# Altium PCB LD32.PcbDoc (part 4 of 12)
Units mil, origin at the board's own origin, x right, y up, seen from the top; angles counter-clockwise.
Board outline 7007.87 x 4368.85 mil, 12 copper layers (Top Layer, Int1 (GND), Int2 (AVDD), Int3 (DVDD), Int4 (GND), Int5 (ST), Int6 (SB), Int8 (AGND), Int7 (AVCC), Int9 (VCCA), Int10 (GND), Bottom Layer), stack 60.136 mil thick; 1165 components, 667 nets, 3910 pads, 2570 vias.
Unrouted connection lines stored in the file: 14.
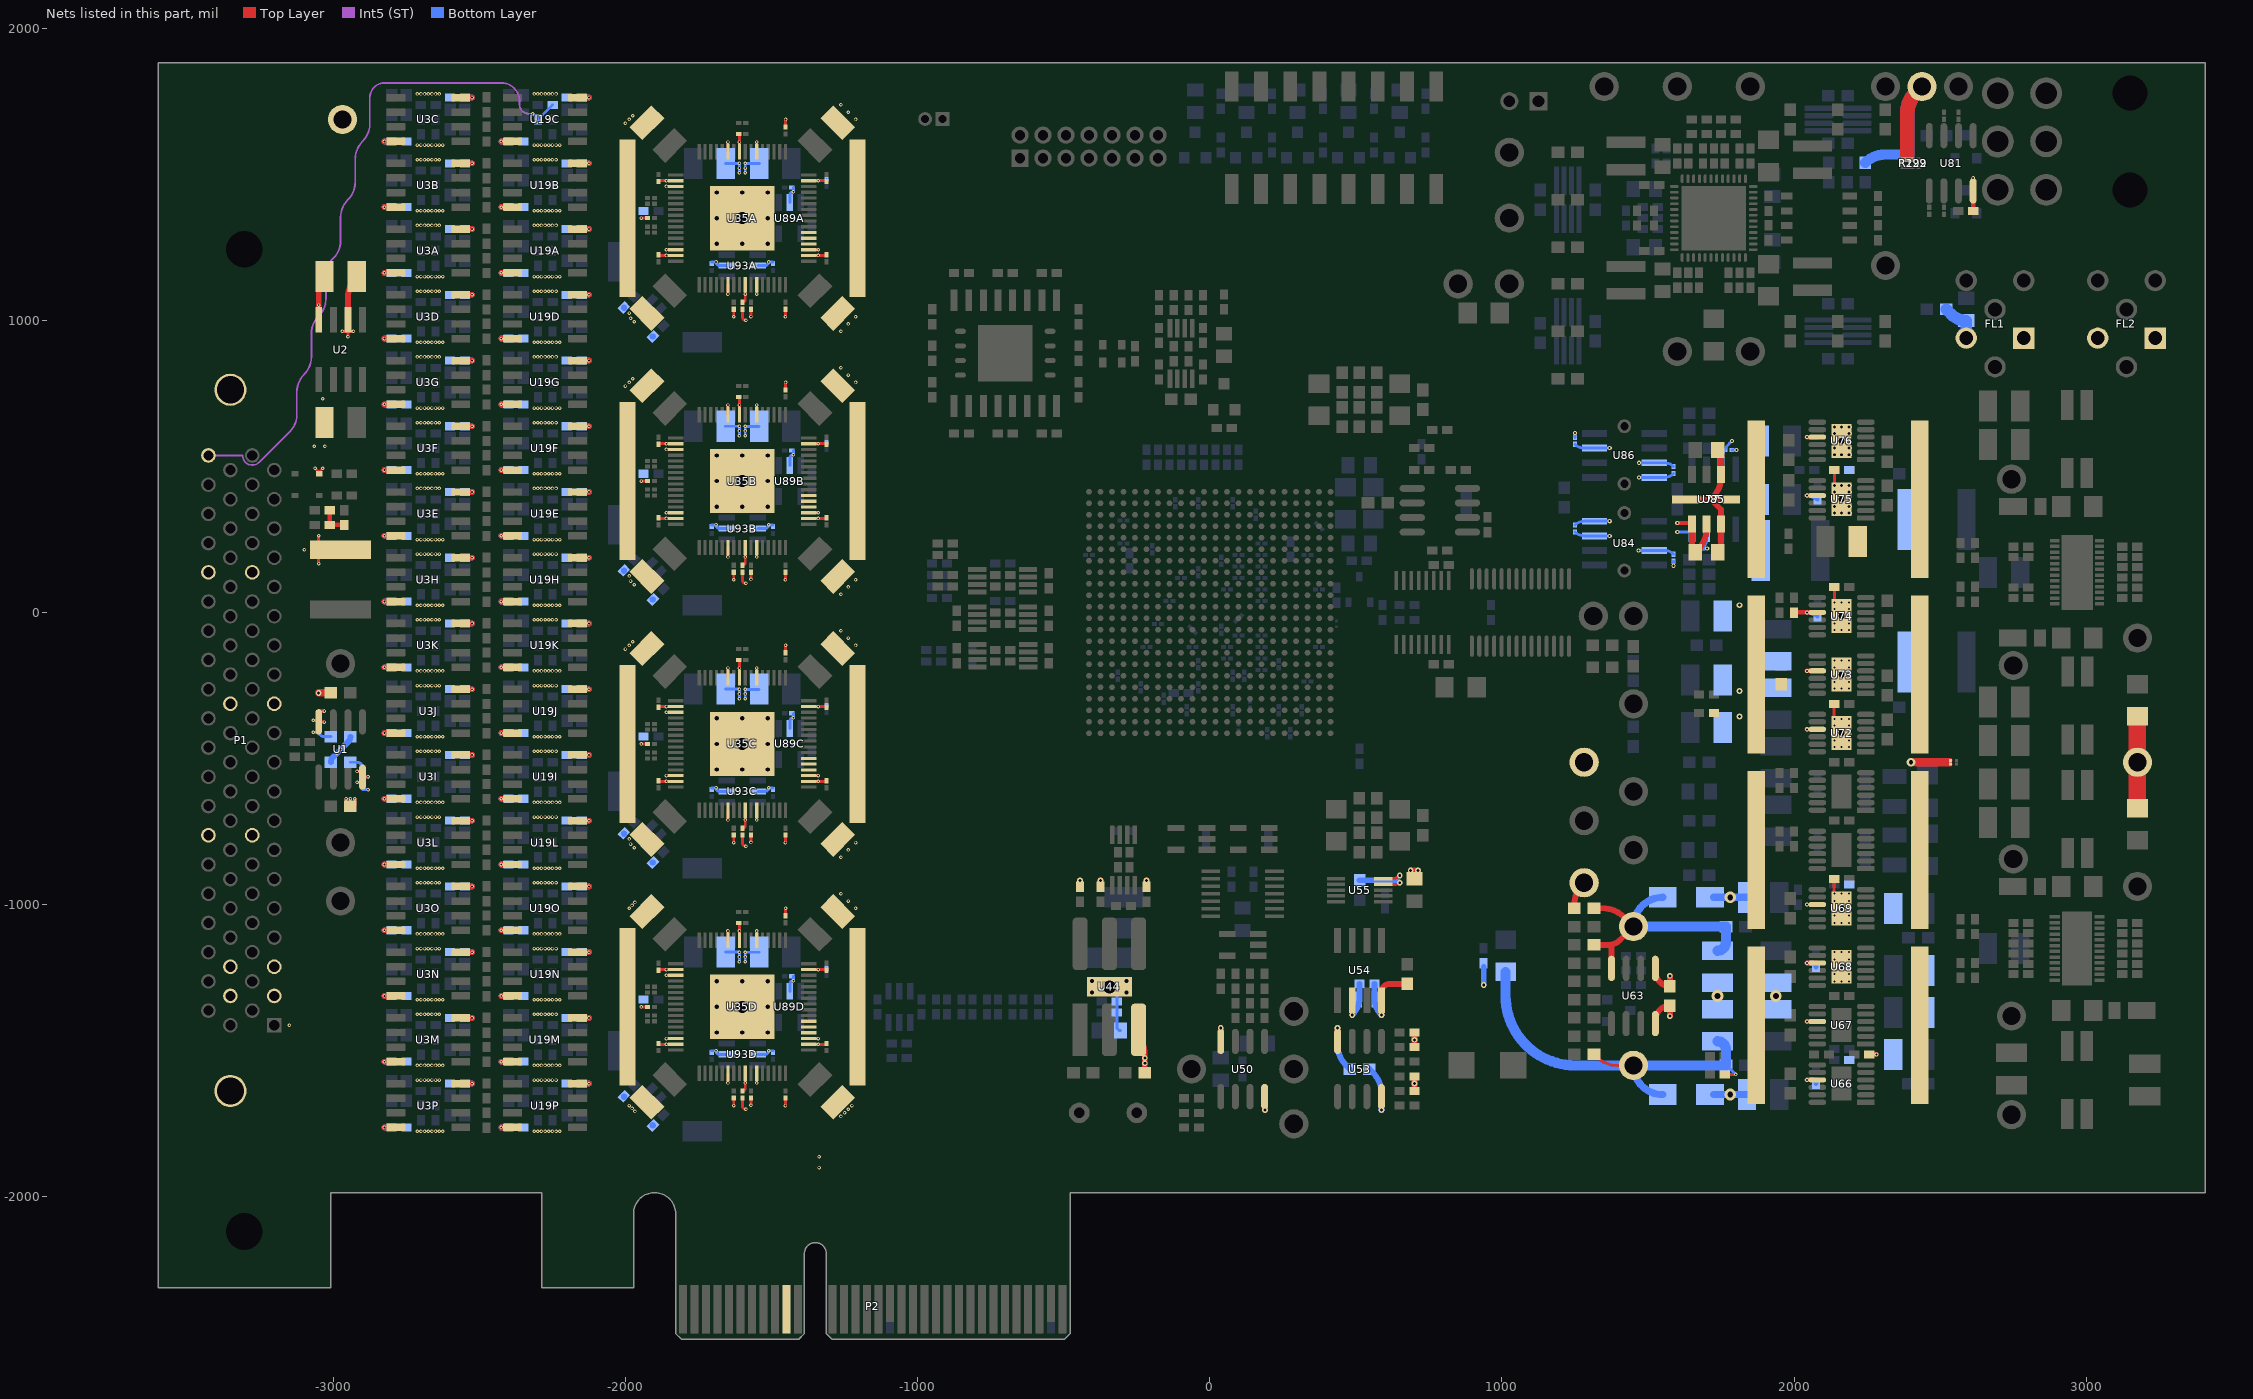
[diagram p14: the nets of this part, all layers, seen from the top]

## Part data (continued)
R213 R215 R216 R218: library part ChipRes1, "R0402 715k", Part Number=ERA-2AEB7150X, Supplier Part Number 1=P715DCCT-ND
R221: library part ChipRes1, "R0603 15k", Part Number=ERA-3AEB153V, Supplier Part Number 1=P15KDBCT-ND
R225 R226: library part ChipRes1, "R0603 0", Part Number=RMCF0603ZT0R00, Supplier Part Number 1=RMCF0603ZT0R00CT-ND
R231: library part ChipRes1, "R0603 34.4k", Part Number=RN73H1JTTD3442F100, Supplier Part Number 1=660-RN73H1JT3442F100
R237: library part ChipRes1, "R0402 12.1k", Part Number=ERA-2AEB1212X, Supplier Part Number 1=P12.1KDCCT-ND
R239: library part ChipRes1, "R0402 33k", Part Number=RT0402FRE0733KL, Supplier Part Number 1=YAG5933CT-ND
R240: library part ChipRes1, "R0402 16.5k", Part Number=RT0402BRD0716K5L, Supplier Part Number 1=YAG4180CT-ND
R243 R245 R262 R270: library part ChipRes1, "R0603 48.1k", Part Number=RT0603BRD0748K1L, Supplier Part Number 1=13-RT0603BRD0748K1LCT-ND
R244: library part ChipRes1, "R0603 59.7k TF", Part Number=RT0603BRD0759K7L, Supplier Part Number 1=13-RT0603BRD0759K7LCT-ND
R251: library part ChipRes1, "R0402 40.2k", Part Number=ERA-2ARC4022X, Supplier Part Number 1=P18270CT-ND
R263: library part ChipRes1, "R0402 9.53k", Part Number=RT0402BRD079K53L, Supplier Part Number 1=YAG4326CT-ND
R264: library part ChipRes1, "R0402 402k", Part Number=RMCF0402FT402KCT-ND
R266: library part ChipRes1, "R0402 301k", Part Number=RMCF0402FT301KCT-ND
R269: library part ChipRes1, "R0402 1.91k", Part Number=RT0402BRD071K91L, Supplier Part Number 1=YAG4201CT-ND
R274 R275: library part ChipRes1, "R0402 30k", Part Number=ERA-2AEB303X, Supplier Part Number 1=P30KDCCT-ND
R284: library part ChipRes1, "R0402 10", Part Number=RP73PF1E10RBTD, Supplier Part Number 1=A127127CT-ND
R308: library part ChipRes1, "R0402  2.67k", Part Number=ERA-2AEB2671X, Supplier Part Number 1=P2.67KDCCT-ND
R317: library part ChipRes1, "R0402 15", Part Number=RP73PF1E15RBTD, Supplier Part Number 1=A127144CT-ND
R335A R335B R335C R335D R335E R335F R335G R335H R335I R335J R335K R335L R335M R335N R335O R335P R383A R383B R383C R383D R383E R383F R383G R383H R383I R383J R383K R383L R383M R383N R383O R383P R399A R399B R399C R399D R399E R399F R399G R399H R399I R399J R399K R399L R399M R399N R399O R399P R447A R447B R447C R447D R447E R447F R447G R447H R447I R447J R447K R447L R447M R447N R447O R447P: library part ChipRes1, "R0603 665", Part Number=RQ73C1J665RBTD, Supplier Part Number 1=A139481CT-ND
S1: "DIP Switch, 8 Position, SPST", Part Number=CKN6128CT-ND
TP1 TP5 TP8 TP9 TP10 TP11 TP15 TP18 TP19 TP20 TP21 TP22 TP24 TP25 TP27 TP28 TP29 TP33 TP34 TP35 TP36 TP37 TP38: library part TP_POSITIVE, "Testpoint, red", Part Number="Keystone / 5000", Supplier Part Number 1=36-5000-ND
TP2 TP3 TP4 TP6 TP7 TP26: library part TP_SIGNAL, "Testpoint, yellow", Part Number="Keystone / 5004", Supplier Part Number 1=36-5004-ND
TP12 TP13 TP14 TP16 TP23 TP30 TP32 TP42: library part TP_GND, "Testpoint, black", Part Number="Keystone / 5001", Supplier Part Number 1=36-5001-ND
TP17 TP31: library part TP_NEGATIVE, "Testpoint, white", Part Number="Keystone / 5002", Supplier Part Number 1=36-5002-ND
TP39 TP40: library part TP_SIGNAL, "Testpoint,SMD, micro miniature", Part Number="Keystone / 5017", Supplier Part Number 1=36-5017CT-ND
TP41A TP41B TP41C TP41D TP45A TP45B TP45C TP45D: library part TP_SMD, "Testpoint,SMD, micro miniature", Part Number=36-5017CT-ND
U1 U50 U53 U57 U63 U81: "Precision Rail-to-Rail Input and Output Operational Amplifier", Part Number=OP284FSZ-REEL7, Supplier Part Number 1=OP284FSZ-REEL7CT-ND
U2 U54: library part ADR292ER, "Low-Noise Micropower Precision Voltage Reference", Part Number=ADR4530ARZ-R7, Supplier Part Number 1=ADR4530ARZ-R7CT-ND
U3A U3B U3C U3D U3E U3F U3G U3H U3I U3J U3K U3L U3M U3N U3O U3P U19A U19B U19C U19D U19E U19F U19G U19H U19I U19J U19K U19L U19M U19N U19O U19P: library part CMP-0808-00013-2, "1.1 nV/rtHz Noise, Low Power, Precision Operational Amplifier, 4.5 to 36 V, -40 to 85 degC, 8-pin SOIC (D8), Green (RoHS & no Sb/Br)", Supplier Part Number 1=296-24959-5-ND
U35A U35B U35C U35D: "Flagship 32-Bit HyperStream II 8-Channel Audio DAC", Part Number=ES9038PRO, Supplier Part Number 1=460-ES9038PRO
U39: library part CMP-12948-000005-1, "IC FLASH 128M SPI 133MHZ 16SOIC", Supplier Part Number 1=MT25QU512ABB8ESF-0SIT-ND
U40: library part CMP-12948-000008-1, "NL"
U41 U42 U43 U46 U47: library part SN65LVDS100, "DIFF TRANSLATOR", Part Number=SN65LVDS100DGKR, Supplier Part Number 1=296-39184-1-ND
U44: library part VCXO_BomarSiTime, "Voltage controlled crystal oscillator, differential output, Bomar 14.3 x 8.7mm, or SiTime 7.0 x 5.0mm", Part Number=B1815-BA0S36LK-67.108864
U45: library part CMP-0364-00012-3, "Artix-7 FPGA, 285 User I/Os, 4 GTP, 484-Ball BGA, Speed Grade 2, Industrial Grade, Pb-Free", Supplier Part Number 1=122-1866-ND
U48 U52 U89A U89B U89C U89D: library part SN65LVDT2DBV, "Single LVDS Receiver with 100 Ohm termination", Part Number=SN65LVDT2DBVR, Supplier Part Number 1=296-6896-1-ND
U49: library part 74F74PC, "Dual D-Type Positive Edge-Triggered Flip-Flop", Supplier Part Number 1=296-1241-1-ND
U51: Part Number=296-9845-1-ND
U55: "16 bit ADC, 250kSPS, pseudo differential, serial", Part Number=AD7685BRMZRL7, Supplier Part Number 1=AD7685BRMZRL7CT-ND
U56: "Quad-Bit Dual Supply Transceiver", Part Number=296-18056-1-ND
U58: library part CMP-0798-00217-1, "1.8 to 5.5 V / 2.5 V, CMOS Low-Voltage 2.5 Ohm, 16-Channel Multiplexer, -40 to 85 degC, 28-pin SOP (RU-28), Tube", Part Number=ADG706BRUZ-REEL7, Supplier Part Number 1=ADG706BRUZ-REEL7CT-ND
U59 U60 U65 U79: library part CMP-0944-00088-2, "Low Power, Precision Instrumentation Amplifier, -40 to 125 degC, 8-pin SOP (DGK8), Green (RoHS & no Sb/Br)", Part Number=INA333QDGKRQ1, Supplier Part Number 1=296-INA333QDGKRQ1CT-ND
U61 U62 U78 U80: "NL"
U64: library part ADP5050ACPZ-R7, "Artix 7 Power Supply", Part Number=ADP5050ACPZ-R7CT-ND, Supplier Part Number 1=505-ADP5052ACPZ-R7CT-ND
U66 U67: library part CMP-09138-000085-1, "IC REG LIN NEG ADJ 500MA 12MSOP", Supplier Part Number 1=505-LT3094IMSE#PBF-ND
U68 U69 U70 U71 U72 U73 U74 U75 U76: library part CMP-09138-000053-1, "IC REG LINEAR 0V 500MA 12MSOP", Part Number=LT3045EMSE-1#PBF, Supplier Part Number 1=505-LT3045EMSE-1#PBF-ND
U77: library part CMP-09137-000088-1, "IC VREF SERIES 0.025% 8CLCC", Supplier Part Number 1=505-LTC6655BHLS8-4.096#PBF-ND
U82 U83: library part LT8582, "Dual 3A Boost/Inverting/SEPIC DC/DC Converter with Fault Protection", Part Number=LT8582EDKD#PBF, Supplier Part Number 1=505-LT8582EDKD#PBF-ND
U84 U85 U86: library part OpAmp, "Op Amp", Part Number=ADA4625-1ARDZ-R7, Supplier Part Number 1=505-ADA4625-1ARDZ-R7CT-ND
U87: library part CMP-0367-00158-2, "1.25 V, 50 ppm / degC, 50 uA Series (Bandgap) Voltage Reference, -40 to 125 degC, 3-pin SOT-23 (DBZ), Green (RoHS & no Sb/Br)", Supplier Part Number 1=REF3012AIDBZTCT-ND
U88 U93A U93B U93C U93D: library part SN74LVC1T45, "Single-Bit Dual Supply Transceiver", Part Number=SN74AVC1T45DBVT, Supplier Part Number 1=296-32277-1-ND
W1 W2: library part NetTie1_small, "Tie two nets together", Part Number=NL
W3: library part NetTie1_small
Y1: library part CMP-06255-000005-1, "MEMS OSC XO 100.0000MHZ CMOS SMD", Supplier Part Number 1=576-4966-5-ND

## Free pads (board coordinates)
  round 113.39 hole 125.2 unplated: MH1(-3304.72,-2118.5) MH2(-3304.72,1243.5)

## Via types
v1: diameter 12, hole 6, Top Layer to Bottom Layer, tented both sides, 1500 vias
v2: diameter 19, hole 10, Top Layer to Bottom Layer, tented both sides, 404 vias
v3: diameter 20, hole 10, Top Layer to Bottom Layer, tented both sides, 337 vias
v4: diameter 14, hole 7, Top Layer to Bottom Layer, tented both sides, 212 vias
v5: diameter 30, hole 15, Top Layer to Bottom Layer, tented both sides, 37 vias
v6: diameter 19.68, hole 7.87, Top Layer to Bottom Layer, 25 vias
v7: diameter 40, hole 20, Top Layer to Bottom Layer, tented both sides, 16 vias
v8: diameter 19.02, hole 10, Top Layer to Bottom Layer, tented both sides, 10 vias
v9: diameter 40, hole 20, Top Layer to Bottom Layer, 9 vias
v10: diameter 60, hole 40, Top Layer to Bottom Layer, 5 vias
v11: diameter 25, hole 13, Top Layer to Bottom Layer, 4 vias
v12: diameter 50, hole 25, Top Layer to Bottom Layer, tented both sides, 4 vias
v13: diameter 35, hole 20, Top Layer to Bottom Layer, 2 vias
v14: diameter 50, hole 25, Top Layer to Bottom Layer, 2 vias
v15: diameter 63, hole 45, Top Layer to Bottom Layer, 1 vias
v16: diameter 14.02, hole 7.01, Top Layer to Bottom Layer, tented both sides, 1 vias
v17: diameter 60, hole 40, Top Layer to Bottom Layer, tented both sides, 1 vias

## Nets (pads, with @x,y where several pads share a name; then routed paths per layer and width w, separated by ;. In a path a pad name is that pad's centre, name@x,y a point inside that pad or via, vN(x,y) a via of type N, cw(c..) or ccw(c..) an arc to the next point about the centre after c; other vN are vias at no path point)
3.3Vaux: P2.B10
12V: C146.1 FL1.1 FL2.1 R199.1 R222.4 R229.1 TP29.1 U81.8 | length 761.7
  Top Layer w10: C146.1@2612.5,1376.43 ccw(c2614.52,1376.43) C146.1@2613.09,1375 ; U81.8@2612.5,1443.01 v1(2612.5,1487.5)
  Top Layer w15: C146.1@2612.5,1376.43 U81.8@2612.5,1443.01
  Top Layer w50: 2387.5,1567.5 2387.5,1708.58 cw(c2487.5,1708.58) 2416.79,1779.29 TP29.1@2437.5,1800
  Bottom Layer w35: R229.1@2243.75,1539.71 cw(c2310.83,1472.63) 2310.83,1567.5 2387.5,1567.5
  Bottom Layer w50: 2387.5,1567.5 2387.5,1708.58 cw(c2487.5,1708.58) 2416.79,1779.29 TP29.1@2437.5,1800
12VA: FL2.2 FR4.1 FR5.1 TP37.1 | length 314.8
  Top Layer w60: FR4.1@3175,-669.88 TP37.1@3175,-512.5 FR5.1@3175,-355.12
12VF: C147.1 FL1.2 R224.2 | length 140.9
  Bottom Layer w40: R224.2@2521.06,1037.5 2538.5,1020.06 ccw(c2589.07,1070.64) C147.1@2589.07,999.11 FL1.2@2589.07,939.07
+7V: C3.1 C9.1 C10.1 C11.1 C97.2 C117.2 C166.2 C188.1 C195.2 C196.2 C335A.1 C335B.1 C335C.1 C335D.1 C335E.1 C335F.1 C335G.1 C335H.1 C335I.1 C335J.1 C335K.1 C335L.1 C335M.1 C335N.1 C335O.1 C335P.1 C415A.1 C415B.1 C415C.1 C415D.1 C415E.1 C415F.1 C415G.1 C415H.1 C415I.1 C415J.1 C415K.1 C415L.1 C415M.1 C415N.1 C415O.1 C415P.1 C480.2 D2.1 D8.2 R134.1 R249.1 TP18.1 U1.8 U2.2 U3A.8 U3B.8 U3C.8 U3D.8 U3E.8 U3F.8 U3G.8 U3H.8 U3I.8 U3J.8 U3K.8 U3L.8 U3M.8 U3N.8 U3O.8 U3P.8 U19A.8 U19B.8 U19C.8 U19D.8 U19E.8 U19F.8 U19G.8 U19H.8 U19I.8 U19J.8 U19K.8 U19L.8 U19M.8 U19N.8 U19O.8 U19P.8 U50.8 U53.8 U54.2 U63.8 U77.1 U77.2 U84.7 U85.7 U86.7 | length 4631.5
  Top Layer w10: v1(-3062.5,493.75) -3051.8,483.05 cw(c-3059.85,475) D2.1@-3048.47,475 cw(c-3032.69,475) -3043.84,486.16 v1(-3036.25,493.75) ; v1(-2968.75,962.5) U2.2@-2950,962.5 ; v1(-2950,943.75) U2.2@-2950,962.5 ; U2.2@-2950,1006.25 U2.2@-2950,1002.36 U2.2@-2950,962.5 ; v1(-2931.25,962.5) U2.2@-2950,962.5 ; v1(-2918.75,-581.25) -2900,-581.25 U1.8@-2900,-563.24 U1.8@-2900,-562.5 ; v1(-2918.75,-543.75) -2900,-543.75 U1.8@-2900,-562.5 ; v1(-2881.25,-562.5) U1.8@-2900,-562.5 ; U77.1@1648.56,287.5 cw(c1648.56,286.06) U77.1@1650,286.06
  Top Layer w15: v4(1600,306.25) 1646.6,306.25 cw(c1646.6,302.85) U77.1@1650,302.85
  Top Layer w20: U2.2@-2950,1006.25 -2950,1078.46 cw(c-2850,1078.46) -2920.71,1149.17 C3.1@-2919.88,1150 ; U3P.8@-2563.78,-1612.5 v1(-2525,-1612.5) ; U3M.8@-2563.78,-1387.5 v1(-2525,-1387.5) ; U3N.8@-2563.78,-1162.5 v1(-2525,-1162.5) ; U3O.8@-2563.78,-937.5 v1(-2525,-937.5) ; U3L.8@-2563.78,-712.5 v1(-2525,-712.5) ; U3I.8@-2563.78,-487.5 v1(-2525,-487.5) ; U3J.8@-2563.78,-262.5 v1(-2525,-262.5) ; U3K.8@-2563.78,-37.5 v1(-2525,-37.5) ; U3H.8@-2563.78,187.5 v1(-2525,187.5) ; U3E.8@-2563.78,412.5 v1(-2525,412.5) ; U3F.8@-2563.78,637.5 v1(-2525,637.5) ; U3G.8@-2563.78,862.5 v1(-2525,862.5) ; U3D.8@-2563.78,1087.5 v1(-2525,1087.5) ; U3A.8@-2563.78,1312.5 v1(-2525,1312.5) ; U3B.8@-2563.78,1537.5 v1(-2525,1537.5) ; U3C.8@-2563.78,1762.5 v1(-2525,1762.5) ; U19P.8@-2163.78,-1612.5 v1(-2125,-1612.5) ; U19M.8@-2163.78,-1387.5 v1(-2125,-1387.5) ; U19N.8@-2163.78,-1162.5 v1(-2125,-1162.5) ; U19O.8@-2163.78,-937.5 v1(-2125,-937.5) ; U19L.8@-2163.78,-712.5 v1(-2125,-712.5) ; U19I.8@-2163.78,-487.5 v1(-2125,-487.5) ; U19J.8@-2163.78,-262.5 v1(-2125,-262.5) ; U19K.8@-2163.78,-37.5 v1(-2125,-37.5) ; U19H.8@-2163.78,187.5 v1(-2125,187.5) ; U19E.8@-2163.78,412.5 v1(-2125,412.5) ; U19F.8@-2163.78,637.5 v1(-2125,637.5) ; U19G.8@-2163.78,862.5 v1(-2125,862.5) ; U19D.8@-2163.78,1087.5 v1(-2125,1087.5) ; U19A.8@-2163.78,1312.5 v1(-2125,1312.5) ; U19B.8@-2163.78,1537.5 v1(-2125,1537.5) ; U19C.8@-2163.78,1762.5 v1(-2125,1762.5) ; U50.8@187.5,-1656.99 v3(188.58,-1702.5) ; U53.8@437.5,-1468.01 v3(437.5,-1422.5) ; v3(487.5,-1377.5) U54.2@487.5,-1327.36 ; R134.1@1314.71,-1137.5 1363.76,-1137.5 ccw(c1363.76,-1080.18) 1375,-1136.39 ; C97.2@1314.71,-1012.5 1346.08,-1012.5 cw(c1346.08,-1112.5) 1416.79,-1041.79 TP18.1@1450,-1075 1404.29,-1120.71 cw(c1363.76,-1080.18) 1375,-1136.39 ; U63.8@1375,-1218.01 1375,-1136.39 ; U77.1@1650,302.85 1650,286.06 1650,234.29 ccw(c1689.65,234.29) C117.2@1661.61,206.25 1670.71,215.35 ccw(c1600,286.06) 1700,286.06 U77.2@1700,302.85
  Bottom Layer w10: C480.2@-2941.54,-512.5 -2918.75,-512.5 cw(c-2918.75,-531.25) -2900,-531.25 -2900,-543.75 ; v1(-2918.75,-581.25) -2900,-581.25 ; v1(-2918.75,-543.75) -2900,-543.75 ; v1(-2881.25,-606.25) -2900,-606.25 -2900,-581.25 ; v1(-2881.25,-562.5) -2900,-562.5 ; C11.1@1250,575.56 ccw(c1281.54,607.1) 1281.54,562.5 v4(1368.75,562.5) ; v4(1467.5,212.5) 1555.96,212.5 cw(c1555.96,167.9) C9.1@1587.5,199.44 ; U85.7@1750,489.86 U85.7@1750,509.14 ; U85.7@1750,524.71 U85.7@1750,509.14 ; C10.1@1763.06,556.25 ccw(c1794.6,524.71) C10.1@1760.15,553.04 ; v4@1786.94,587.5 1779.29,579.85 ccw(c1850,509.14) C10.1@1760.15,553.04 ; -2900,-581.25 -2900,-562.5 ; -2900,-562.5 -2900,-543.75 ; U85.7@1750,509.14 cw(c1850,509.14) C10.1@1760.15,553.04
  Bottom Layer w20: C415P.1@-2549.41,-1612.5 v1(-2525,-1612.5) ; C415M.1@-2549.41,-1387.5 v1(-2525,-1387.5) ; C415N.1@-2549.41,-1162.5 v1(-2525,-1162.5) ; C415O.1@-2549.41,-937.5 v1(-2525,-937.5) ; C415L.1@-2549.41,-712.5 v1(-2525,-712.5) ; C415I.1@-2549.41,-487.5 v1(-2525,-487.5) ; C415J.1@-2549.41,-262.5 v1(-2525,-262.5) ; C415K.1@-2549.41,-37.5 v1(-2525,-37.5) ; C415H.1@-2549.41,187.5 v1(-2525,187.5) ; C415E.1@-2549.41,412.5 v1(-2525,412.5) ; C415F.1@-2549.41,637.5 v1(-2525,637.5) ; C415G.1@-2549.41,862.5 v1(-2525,862.5) ; C415D.1@-2549.41,1087.5 v1(-2525,1087.5) ; C415A.1@-2549.41,1312.5 v1(-2525,1312.5) ; C415B.1@-2549.41,1537.5 v1(-2525,1537.5) ; C415C.1@-2549.41,1762.5 v1(-2525,1762.5) ; C335P.1@-2149.41,-1612.5 v1(-2125,-1612.5) ; C335M.1@-2149.41,-1387.5 v1(-2125,-1387.5) ; C335N.1@-2149.41,-1162.5 v1(-2125,-1162.5) ; C335O.1@-2149.41,-937.5 v1(-2125,-937.5) ; C335L.1@-2149.41,-712.5 v1(-2125,-712.5) ; C335I.1@-2149.41,-487.5 v1(-2125,-487.5) ; C335J.1@-2149.41,-262.5 v1(-2125,-262.5) ; C335K.1@-2149.41,-37.5 v1(-2125,-37.5) ; C335H.1@-2149.41,187.5 v1(-2125,187.5) ; C335E.1@-2149.41,412.5 v1(-2125,412.5) ; C335F.1@-2149.41,637.5 v1(-2125,637.5) ; C335G.1@-2149.41,862.5 v1(-2125,862.5) ; C335D.1@-2149.41,1087.5 v1(-2125,1087.5) ; C335A.1@-2149.41,1312.5 v1(-2125,1312.5) ; C335B.1@-2149.41,1537.5 v1(-2125,1537.5) ; C335C.1@-2149.41,1762.5 v1(-2125,1762.5) ; v3(437.5,-1422.5) 437.5,-1479.44 ccw(c537.5,-1479.44) 466.79,-1550.16 C195.2@479.13,-1562.5 ; v3(487.5,-1377.5) ccw(c426.91,-1316.91) 512.6,-1316.91 C196.2@512.6,-1270.69
  Bottom Layer w25: TP18.1@1450,-1075 cw(c1550,-1075) 1550,-975 D8.2@1550.54,-975
  Bottom Layer w35: TP18.1@1450,-1075 R249.1@1766.54,-1075 1766.54,-1128.35 cw(c1737.5,-1128.35) C166.2@1737.5,-1157.38
  other v4: 1787.5,587.5
-7V: C12.1 C13.1 C14.1 C105.2 C165.1 C367A.1 C367B.1 C367C.1 C367D.1 C367E.1 C367F.1 C367G.1 C367H.1 C367I.1 C367J.1 C367K.1 C367L.1 C367M.1 C367N.1 C367O.1 C367P.1 C447A.1 C447B.1 C447C.1 C447D.1 C447E.1 C447F.1 C447G.1 C447H.1 C447I.1 C447J.1 C447K.1 C447L.1 C447M.1 C447N.1 C447O.1 C447P.1 C479.2 D9.1 FR6.1 R140.2 R143.1 R248.1 TP17.1 U1.4 U3A.4 U3B.4 U3C.4 U3D.4 U3E.4 U3F.4 U3G.4 U3H.4 U3I.4 U3J.4 U3K.4 U3L.4 U3M.4 U3N.4 U3O.4 U3P.4 U19A.4 U19B.4 U19C.4 U19D.4 U19E.4 U19F.4 U19G.4 U19H.4 U19I.4 U19J.4 U19K.4 U19L.4 U19M.4 U19N.4 U19O.4 U19P.4 U63.4 U84.4 U85.4 U86.4 | length 4287.6
  Top Layer w10: v1(-3068.75,-410) -3050,-410 U1.4@-3050,-375 ; v1(-3068.75,-368.75) U1.4@-3050,-368.75 ; v1(-3031.25,-375) U1.4@-3050,-375 ; v1(-3031.25,-337.5) -3050,-337.5 U1.4@-3050,-368.75 ; R140.2@1314.71,-1512.5 1322.93,-1520.71 ccw(c1393.64,-1450) 1393.64,-1550 TP17.1@1450,-1550 ; R143.1@1763.09,-1581.25 v1(1800,-1581.25) ; U1.4@-3050,-375 U1.4@-3050,-374.26 U1.4@-3050,-368.75
  Top Layer w20: v1(-2825,-1762.5) U3P.4@-2786.22,-1762.5 ; v1(-2825,-1537.5) U3M.4@-2786.22,-1537.5 ; v1(-2825,-1312.5) U3N.4@-2786.22,-1312.5 ; v1(-2825,-1087.5) U3O.4@-2786.22,-1087.5 ; v1(-2825,-862.5) U3L.4@-2786.22,-862.5 ; v1(-2825,-637.5) U3I.4@-2786.22,-637.5 ; v1(-2825,-412.5) U3J.4@-2786.22,-412.5 ; v1(-2825,-187.5) U3K.4@-2786.22,-187.5 ; v1(-2825,37.5) U3H.4@-2786.22,37.5 ; v1(-2825,262.5) U3E.4@-2786.22,262.5 ; v1(-2825,487.5) U3F.4@-2786.22,487.5 ; v1(-2825,712.5) U3G.4@-2786.22,712.5 ; v1(-2825,937.5) U3D.4@-2786.22,937.5 ; v1(-2825,1162.5) U3A.4@-2786.22,1162.5 ; v1(-2825,1387.5) U3B.4@-2786.22,1387.5 ; v1(-2825,1612.5) U3C.4@-2786.22,1612.5 ; v1(-2425,-1762.5) U19P.4@-2386.22,-1762.5 ; v1(-2425,-1537.5) U19M.4@-2386.22,-1537.5 ; v1(-2425,-1312.5) U19N.4@-2386.22,-1312.5 ; v1(-2425,-1087.5) U19O.4@-2386.22,-1087.5 ; v1(-2425,-862.5) U19L.4@-2386.22,-862.5 ; v1(-2425,-637.5) U19I.4@-2386.22,-637.5 ; v1(-2425,-412.5) U19J.4@-2386.22,-412.5 ; v1(-2425,-187.5) U19K.4@-2386.22,-187.5 ; v1(-2425,37.5) U19H.4@-2386.22,37.5 ; v1(-2425,262.5) U19E.4@-2386.22,262.5 ; v1(-2425,487.5) U19F.4@-2386.22,487.5 ; v1(-2425,712.5) U19G.4@-2386.22,712.5 ; v1(-2425,937.5) U19D.4@-2386.22,937.5 ; v1(-2425,1162.5) U19A.4@-2386.22,1162.5 ; v1(-2425,1387.5) U19B.4@-2386.22,1387.5 ; v1(-2425,1612.5) U19C.4@-2386.22,1612.5 ; U63.4@1525,-1395.82 cw(c1575,-1395.82) C105.2@1575,-1345.82 v8(1575,-1381.25)
  Bottom Layer w10: v1(-3068.75,-410) -3050,-410 -3050,-406.25 ; v1(-3068.75,-368.75) -3050,-368.75 ; v1(-3031.25,-337.5) -3050,-337.5 -3050,-368.75 ; C479.2@-3008.46,-425 -3031.25,-425 cw(c-3031.25,-406.25) -3050,-406.25 ; C14.1@1250,299.44 cw(c1281.54,267.9) 1281.54,312.5 v4(1368.75,312.5) ; v4(1468.75,462.5) 1555.96,462.5 ccw(c1555.96,507.1) C13.1@1587.5,475.56 ; v4(1600,275) U85.4@1650,275 ; U85.4@1650,275.59 U85.4@1650,275 ; U85.4@1650,285.14 U85.4@1650,275 ; C12.1@1663.06,218.75 cw(c1694.6,250.29) 1650,250.29 U85.4@1650,275 ; R248.1@1766.54,-1550 cw(c1766.54,-1555.35) 1770.31,-1551.56 v1(1800,-1581.25) ; -3050,-406.25 -3050,-368.75
  Bottom Layer w20: v1(-2825,-1762.5) C447P.1@-2800.59,-1762.5 ; v1(-2825,-1537.5) C447M.1@-2800.59,-1537.5 ; v1(-2825,-1312.5) C447N.1@-2800.59,-1312.5 ; v1(-2825,-1087.5) C447O.1@-2800.59,-1087.5 ; v1(-2825,-862.5) C447L.1@-2800.59,-862.5 ; v1(-2825,-637.5) C447I.1@-2800.59,-637.5 ; v1(-2825,-412.5) C447J.1@-2800.59,-412.5 ; v1(-2825,-187.5) C447K.1@-2800.59,-187.5 ; v1(-2825,37.5) C447H.1@-2800.59,37.5 ; v1(-2825,262.5) C447E.1@-2800.59,262.5 ; v1(-2825,487.5) C447F.1@-2800.59,487.5 ; v1(-2825,712.5) C447G.1@-2800.59,712.5 ; v1(-2825,937.5) C447D.1@-2800.59,937.5 ; v1(-2825,1162.5) C447A.1@-2800.59,1162.5 ; v1(-2825,1387.5) C447B.1@-2800.59,1387.5 ; v1(-2825,1612.5) C447C.1@-2800.59,1612.5 ; v1(-2425,-1762.5) C367P.1@-2400.59,-1762.5 ; v1(-2425,-1537.5) C367M.1@-2400.59,-1537.5 ; v1(-2425,-1312.5) C367N.1@-2400.59,-1312.5 ; v1(-2425,-1087.5) C367O.1@-2400.59,-1087.5 ; v1(-2425,-862.5) C367L.1@-2400.59,-862.5 ; v1(-2425,-637.5) C367I.1@-2400.59,-637.5 ; v1(-2425,-412.5) C367J.1@-2400.59,-412.5 ; v1(-2425,-187.5) C367K.1@-2400.59,-187.5 ; v1(-2425,37.5) C367H.1@-2400.59,37.5 ; v1(-2425,262.5) C367E.1@-2400.59,262.5 ; v1(-2425,487.5) C367F.1@-2400.59,487.5 ; v1(-2425,712.5) C367G.1@-2400.59,712.5 ; v1(-2425,937.5) C367D.1@-2400.59,937.5 ; v1(-2425,1162.5) C367A.1@-2400.59,1162.5 ; v1(-2425,1387.5) C367B.1@-2400.59,1387.5 ; v1(-2425,1612.5) C367C.1@-2400.59,1612.5
  Bottom Layer w25: TP17.1@1450,-1550 ccw(c1550,-1550) 1550,-1650 D9.1@1550.54,-1650
  Bottom Layer w35: FR6.1@1012.5,-1230.12 1012.5,-1312.36 ccw(c1250.14,-1312.36) 1250.14,-1550 TP17.1@1450,-1550 R248.1@1766.54,-1550 1766.54,-1496.65 ccw(c1737.5,-1496.65) C165.1@1737.5,-1467.62
ADRA: R63A.2 U35A.41 | length 66.2
  Top Layer w10: R63A.2@-1600,1061.94 ccw(c-1600,1071.78) -1590.16,1071.78 -1590.16,1086.93 v1(-1590.16,1090) U35A.41@-1590.16,1122.5
ADRB: R63B.2 U35B.41 | length 66.2
  Top Layer w10: R63B.2@-1600,161.94 ccw(c-1600,171.78) -1590.16,171.78 -1590.16,186.93 v1(-1590.16,190) U35B.41@-1590.16,222.5
ADRC: R63C.2 U35C.41 | length 66.2
  Top Layer w10: R63C.2@-1600,-738.06 ccw(c-1600,-728.22) -1590.16,-728.22 -1590.16,-713.07 v1(-1590.16,-710) U35C.41@-1590.16,-677.5
ADRD: R63D.2 U35D.41 | length 66.2
  Top Layer w10: R63D.2@-1600,-1638.06 ccw(c-1600,-1628.22) -1590.16,-1628.22 -1590.16,-1613.07 v1(-1590.16,-1610) U35D.41@-1590.16,-1577.5
AGND: C1.1 C2.2 C3.2 C4.2 C5.1 C6.2 C7A.1 C7B.1 C7C.1 C7D.1 C8A.2 C8B.2 C8C.2 C8D.2 C9.2 C10.2 C11.2 C12.2 C13.2 C14.2 C15A.1 C15B.1 C15C.1 C15D.1 C19A.1 C19B.1 C19C.1 C19D.1 C20A.1 C20B.1 C20C.1 C20D.1 C27A.1 C27B.1 C27C.1 C27D.1 C31A.1 C31B.1 C31C.1 C31D.1 C35A.2 C35B.2 C35C.2 C35D.2 C36A.2 C36B.2 C36C.2 C36D.2 C43A.2 C43B.2 C43C.2 C43D.2 C44A.1 C44B.1 C44C.1 C44D.1 C51A.1 C51B.1 C51C.1 C51D.1 C52A.1 C52B.1 C52C.1 C52D.1 C64.1 C86.1 C87.1 C88.1 C89.1 C90.2 C97.1 C105.1 C116.2 C117.1 C144.1 C145.2 C150.1 C151.2 C156.1 C157.2 C158.1 C161.1 C162.1 C165.2 C166.1 C167.1 C168.1 C169.1 C170.1 C171.1 C181.1 C188.2 C195.1 C196.1 C198.1 C267.1 C272.2 C287A.2 C287B.2 C287C.2 C287D.2 C291A.1 C291B.1 C291C.1 C291D.1 C295A.2 C295B.2 C295C.2 C295D.2 C299A.1 C299B.1 C299C.1 C299D.1 C303A.1 C303B.1 C303C.1 C303D.1 C307A.1 C307B.1 C307C.1 C307D.1 C311A.2 C311B.2 C311C.2 C311D.2 C315A.2 C315B.2 C315C.2 C315D.2 C335A.2 C335B.2 C335C.2 C335D.2 C335E.2 C335F.2 C335G.2 C335H.2 C335I.2 C335J.2 C335K.2 C335L.2 C335M.2 C335N.2 C335O.2 C335P.2 C367A.2 C367B.2 C367C.2 C367D.2 C367E.2 C367F.2 C367G.2 C367H.2 C367I.2 C367J.2 C367K.2 C367L.2 C367M.2 C367N.2 C367O.2 C367P.2 C415A.2 C415B.2 C415C.2 C415D.2 C415E.2 C415F.2 C415G.2 C415H.2 C415I.2 C415J.2 C415K.2 C415L.2 C415M.2 C415N.2 C415O.2 C415P.2 C447A.2 C447B.2 C447C.2 C447D.2 C447E.2 C447F.2 C447G.2 C447H.2 C447I.2 C447J.2 C447K.2 C447L.2 C447M.2 C447N.2 C447O.2 C447P.2 C479.1 C480.1 C481.2 C482.1 C483.1 C484.2 C500.1 D8.1 D9.2 MP4A.1 MP4A.2 MP4B.1 MP4B.2 MP4C.1 MP4C.2 MP4D.1 MP4D.2 MP5.1 MP5.2 MP6.1 MP6.2 MP7.1 MP7.2 MP8.1 MP8.2 P1.5 P1.6 P1.9 P1.10 P1.27 P1.28 P1.45 P1.46 P1.63 P1.64 P1.81 P1.82 R3.1 R6.1 R55A.1 R55B.1 R55C.1 R55D.1 R63A.1 R63B.1 R63C.1 R63D.1 R91.1 R94.2 R97.2 R117.2 R149.2 R151.2 R160.2 R172.2 R177.2 R178.2 R179.2 R181.1 R186.1 R232.2 R234.2 R239.1 R240.1 R241.2 R242.1 R303.2 R327A.1 R327B.1 R327C.1 R327D.1 TP12.1 TP14.1 TP42.1 U2.4 U35A.6 U35A.9 U35A.11 U35A.18 U35A.19 U35A.30 U35A.31 U35A.38 U35A.43 U35A.50 U35A.51 U35A.52 U35A.53 U35A.54 U35A.63 U35A.65 U35B.6 U35B.9 U35B.11 U35B.18 U35B.19 U35B.30 U35B.31 U35B.38 U35B.43 U35B.50 U35B.51 U35B.52 U35B.53 U35B.54 U35B.63 U35B.65 U35C.6 U35C.9 U35C.11 U35C.18 U35C.19 U35C.30 U35C.31 U35C.38 U35C.43 U35C.50 U35C.51 U35C.52 U35C.53 U35C.54 U35C.63 U35C.65 U35D.6 U35D.9 U35D.11 U35D.18 U35D.19 U35D.30 U35D.31 U35D.38 U35D.43 U35D.50 U35D.51 U35D.52 U35D.53 U35D.54 U35D.63 U35D.65 U44.3 U44.7 U50.4 U53.4 U54.4 U55.4 U55.5 U63.5 U66.9 U67.9 U68.9 U68.13 U69.9 U69.13 U72.9 U72.13 U73.9 U73.13 U74.9 U74.13 U75.9 U75.13 U76.9 U76.13 U77.3 U77.4 U77.5 U77.8 U84.3 U85.3 U86.3 U89A.2 U89B.2 U89C.2 U89D.2 U93A.2 U93A.5 U93B.2 U93B.5 U93C.2 U93C.5 U93D.2 U93D.5 W1.2 W2.2 | length 8504.6
  Top Layer w10: v1(-3050,167.5) v1(-3050,262.5) ; v1(-2956.25,-637.5) -2956.25,-662.5 C4.2@-2941.54,-662.5 ; v1(-2941.25,-637.5) -2941.54,-637.5 C4.2@-2941.54,-662.5 ; v1(-2926.25,-637.5) -2926.25,-662.5 C4.2@-2941.54,-662.5 ; v1(-1946.08,-1350) C15D.1@-1930,-1350 ; v1(-1946.08,-450) C15C.1@-1930,-450 ; v1(-1946.08,450) C15B.1@-1930,450 ; v1(-1946.08,1350) C15A.1@-1930,1350 ; C19D.1@-1887.5,-1475.56 ccw(c-1885.11,-1475.56) -1885.11,-1477.95 -1868.3,-1477.95 v1(-1860,-1477.95) U35D.31@-1827.5,-1477.95 ; C20D.1@-1887.5,-1224.44 cw(c-1885.11,-1224.44) -1885.11,-1222.05 -1868.3,-1222.05 v1(-1860,-1222.05) U35D.18@-1827.5,-1222.05 ; C19C.1@-1887.5,-575.56 ccw(c-1885.11,-575.56) -1885.11,-577.95 -1868.3,-577.95 v1(-1860,-577.95) U35C.31@-1827.5,-577.95 ; C20C.1@-1887.5,-324.44 cw(c-1885.11,-324.44) -1885.11,-322.05 -1868.3,-322.05 v1(-1860,-322.05) U35C.18@-1827.5,-322.05 ; C19B.1@-1887.5,324.44 ccw(c-1885.11,324.44) -1885.11,322.05 -1868.3,322.05 v1(-1860,322.05) U35B.31@-1827.5,322.05 ; C20B.1@-1887.5,575.56 cw(c-1885.11,575.56) -1885.11,577.95 -1868.3,577.95 v1(-1860,577.95) U35B.18@-1827.5,577.95 ; C19A.1@-1887.5,1224.44 ccw(c-1885.11,1224.44) -1885.11,1222.05 -1868.3,1222.05 v1(-1860,1222.05) U35A.31@-1827.5,1222.05 ; C20A.1@-1887.5,1475.56 cw(c-1885.11,1475.56) -1885.11,1477.95 -1868.3,1477.95 v1(-1860,1477.95) U35A.18@-1827.5,1477.95 ; v1(-1860,-1458.27) U35D.30@-1827.5,-1458.27 ; v1(-1860,-1241.73) U35D.19@-1827.5,-1241.73 ; v1(-1860,-558.27) U35C.30@-1827.5,-558.27 ; v1(-1860,-341.73) U35C.19@-1827.5,-341.73 ; v1(-1860,341.73) U35B.30@-1827.5,341.73 ; v1(-1860,558.27) U35B.19@-1827.5,558.27 ; v1(-1860,1241.73) U35A.30@-1827.5,1241.73 ; v1(-1860,1458.27) U35A.19@-1827.5,1458.27 ; v1(-1649.21,-1610) U35D.38@-1649.21,-1577.5 ; U35D.11@-1649.21,-1122.5 v1(-1649.21,-1090) ; v1(-1649.21,-710) U35C.38@-1649.21,-677.5 ; U35C.11@-1649.21,-222.5 v1(-1649.21,-190) ; v1(-1649.21,190) U35B.38@-1649.21,222.5 ; U35B.11@-1649.21,677.5 v1(-1649.21,710) ; v1(-1649.21,1090) U35A.38@-1649.21,1122.5 ; U35A.11@-1649.21,1577.5 v1(-1649.21,1610) ; v1(-1629.53,-1687.5) C27D.1@-1629.53,-1667.5 ; v1(-1629.53,-787.5) C27C.1@-1629.53,-767.5 ; v1(-1629.53,112.5) C27B.1@-1629.53,132.5 ; v1(-1629.53,1012.5) C27A.1@-1629.53,1032.5 ; R55D.1@-1611.94,-1062.5 cw(c-1611.94,-1064.59) -1609.84,-1064.59 -1609.84,-1088.64 v1(-1609.84,-1090) U35D.9@-1609.84,-1122.5 ; R55C.1@-1611.94,-162.5 cw(c-1611.94,-164.59) -1609.84,-164.59 -1609.84,-188.64 v1(-1609.84,-190) U35C.9@-1609.84,-222.5 ; R55B.1@-1611.94,737.5 cw(c-1611.94,735.41) -1609.84,735.41 -1609.84,711.36 v1(-1609.84,710) U35B.9@-1609.84,677.5 ; R55A.1@-1611.94,1637.5 cw(c-1611.94,1635.41) -1609.84,1635.41 -1609.84,1611.36 v1(-1609.84,1610) U35A.9@-1609.84,1577.5 ; R63D.1@-1600,-1661.94 -1600,-1687.5 ccw(c-1587.5,-1687.5) v1(-1587.5,-1700) ; R63C.1@-1600,-761.94 -1600,-787.5 ccw(c-1587.5,-787.5) v1(-1587.5,-800) ; R63B.1@-1600,138.06 -1600,112.5 ccw(c-1587.5,112.5) v1(-1587.5,100) ; R63A.1@-1600,1038.06 -1600,1012.5 ccw(c-1587.5,1012.5) v1(-1587.5,1000) ; v1(-1570.47,-1686.91) C31D.1@-1570.47,-1667.5 ; v1(-1570.47,-786.91) C31C.1@-1570.47,-767.5 ; v1(-1570.47,113.09) C31B.1@-1570.47,132.5 ; v1(-1570.47,1013.09) C31A.1@-1570.47,1032.5 ; v1(-1550.79,-1610) U35D.43@-1550.79,-1577.5 ; U35D.6@-1550.79,-1122.5 v1(-1550.79,-1090) ; v1(-1550.79,-710) U35C.43@-1550.79,-677.5 ; U35C.6@-1550.79,-222.5 v1(-1550.79,-190) ; v1(-1550.79,190) U35B.43@-1550.79,222.5 ; U35B.6@-1550.79,677.5 v1(-1550.79,710) ; v1(-1550.79,1090) U35A.43@-1550.79,1122.5 ; U35A.6@-1550.79,1577.5 v1(-1550.79,1610) ; v1(-1452.5,-1687.5) -1452.21,-1687.21 C35D.2@-1452.21,-1667.5 ; v1(-1452.5,-787.5) -1452.21,-787.21 C35C.2@-1452.21,-767.5 ; v1(-1452.5,112.5) -1452.21,112.79 C35B.2@-1452.21,132.5 ; v1(-1452.5,1012.5) -1452.21,1012.79 C35A.2@-1452.21,1032.5 ; C36D.2@-1452.21,-1032.5 v1(-1452.21,-1012.38) ; C36C.2@-1452.21,-132.5 v1(-1452.21,-112.38) ; C36B.2@-1452.21,767.5 v1(-1452.21,787.62) ; C36A.2@-1452.21,1667.5 v1(-1452.21,1687.62) ; U35D.50@-1372.5,-1477.95 v1(-1340,-1477.95) -1331.7,-1477.95 -1314.89,-1477.95 ccw(c-1314.89,-1475.56) C51D.1@-1312.5,-1475.56 ; U35D.51@-1372.5,-1458.27 v1(-1340,-1458.27) ; U35D.63@-1372.5,-1222.05 v1(-1340,-1222.05) -1331.7,-1222.05 -1314.89,-1222.05 cw(c-1314.89,-1224.44) C52D.1@-1312.5,-1224.44 ; U35C.50@-1372.5,-577.95 v1(-1340,-577.95) -1331.7,-577.95 -1314.89,-577.95 ccw(c-1314.89,-575.56) C51C.1@-1312.5,-575.56 ; U35C.51@-1372.5,-558.27 v1(-1340,-558.27) ; U35C.63@-1372.5,-322.05 v1(-1340,-322.05) -1331.7,-322.05 -1314.89,-322.05 cw(c-1314.89,-324.44) C52C.1@-1312.5,-324.44 ; U35B.50@-1372.5,322.05 v1(-1340,322.05) -1331.7,322.05 -1314.89,322.05 ccw(c-1314.89,324.44) C51B.1@-1312.5,324.44 ; U35B.51@-1372.5,341.73 v1(-1340,341.73) ; U35B.63@-1372.5,577.95 v1(-1340,577.95) -1331.7,577.95 -1314.89,577.95 cw(c-1314.89,575.56) C52B.1@-1312.5,575.56 ; U35A.50@-1372.5,1222.05 v1(-1340,1222.05) -1331.7,1222.05 -1314.89,1222.05 ccw(c-1314.89,1224.44) C51A.1@-1312.5,1224.44 ; U35A.51@-1372.5,1241.73 v1(-1340,1241.73) ; U35A.63@-1372.5,1477.95 v1(-1340,1477.95) -1331.7,1477.95 -1314.89,1477.95 cw(c-1314.89,1475.56) C52A.1@-1312.5,1475.56 ; U55.4@593.21,-930.31 637.17,-930.31 ccw(c637.17,-912.17) v3(650,-925) ; U55.5@593.21,-910.63 624.34,-910.63 ccw(c624.34,-874.34) v3(650,-900) ; R181.1@2136.91,-912.5 2136.91,-962.5 v4(2137.5,-962.5) ; R177.2@2136.91,-312.5 2136.91,-365 v4(2137.5,-365) ; R178.2@2136.91,87.5 2137.5,87.5 v4(2137.5,35) ; R179.2@2136.91,487.5 2137.5,487.5 v3(2137.5,435)
  Top Layer w15: C2.2@-3011.91,350 R3.1@-3011.91,300 R6.1@-2963.09,300 ; R172.2@2000,-0.59 cw(c2002.14,-2.73) 2002.14,0.3 v4(2043.75,0.3) U74.9@2079.44,0.3 ; v4(2043.75,-399.7) U72.9@2079.44,-399.7 ; v4(2043.75,-199.7) U73.9@2079.44,-199.7 ; v4(2043.75,400.3) U75.9@2079.44,400.3 ; v4(2043.75,600.3) U76.9@2079.44,600.3 ; W1.2@2535,-518.75 2415.09,-518.75 cw(c2415.09,-497.41) v5(2400,-512.5) cw(c2415.09,-527.59) 2415.09,-506.25 W2.2@2535,-506.25
  Top Layer w16: v4(2043.75,-1599.7) U66.9@2079.44,-1599.7 ; v4(2043.75,-1400) U67.9@2079.14,-1400 ; v4(2043.75,-1199.7) U68.9@2079.44,-1199.7 ; R186.1@2256.84,-1512.5 v4(2281.25,-1512.5)
  Top Layer w20: U2.4@-3050,1002.36 v1(-3050,1052.5) -3050,1102 cw(c-2982.12,1102) C3.2@-3030.12,1150 ; C64.1@-444.88,-938.98 ccw(c-445.83,-938.03) -444.49,-938.03 v3(-444.49,-917.32) ; R91.1@-374.02,-938.98 v3(-374.02,-917.32) ; U44.3@-246.46,-1452.76 cw(c-304.44,-1510.74) -222.44,-1510.74 R94.2@-222.44,-1574.8 ; R97.2@-216.54,-938.98 v3(-216.54,-917.32) ; U50.4@37.5,-1468.01 v3(37.5,-1422.5) ; v3(587.5,-1377.5) U54.4@587.5,-1327.36 587.5,-1300 cw(c616.54,-1300) 616.54,-1270.96 C89.1@675,-1270.96 ; C86.1@700.59,-1637.5 C87.1@700.59,-1587.5 ; R117.2@700.59,-1487.5 C88.1@700.59,-1437.5 ; C97.1@1247.79,-1012.5 1247.79,-999.89 cw(c1347.79,-999.89) 1277.07,-929.18 TP12.1@1281.25,-925 ; U63.5@1525,-1228.89 ccw(c1575,-1228.89) C105.1@1575,-1278.89 v8(1575,-1243.75) ; U77.8@1631.1,387.5 v3(1715.16,387.5) ; C117.1@1738.39,206.25 ccw(c1710.35,234.29) 1750,234.29 1750,352.66 v3(1715.16,387.5) ; C116.2@1738.39,556.25 cw(c1710.35,528.21) 1750,528.21 U77.5@1750,472.15 1750,463.76 cw(c1650,463.76) 1720.71,393.05 v3(1715.16,387.5) ; U77.4@1784.65,387.5 v3(1715.16,387.5) ; v3(687.5,-882.5) ccw(c727.61,-882.5) 699.25,-910.86 C90.2@700,-911.61 700.75,-910.86 ccw(c672.39,-882.5) v3(712.5,-882.5) v3(687.5,-882.5)
  Top Layer w25: v3(-3050,-275) C6.2@-3008.46,-275
  Bottom Layer w10: C307D.1@-1705,-1500 v1(-1690,-1500) ccw(c-1677.5,-1500) -1677.5,-1512.5 U93D.2@-1653.15,-1512.5 ; C307C.1@-1705,-600 v1(-1690,-600) ccw(c-1677.5,-600) -1677.5,-612.5 U93C.2@-1653.15,-612.5 ; C307B.1@-1705,300 v1(-1690,300) ccw(c-1677.5,300) -1677.5,287.5 U93B.2@-1653.15,287.5 ; C307A.1@-1705,1200 v1(-1690,1200) ccw(c-1677.5,1200) -1677.5,1187.5 U93A.2@-1653.15,1187.5 ; C303D.1@-1657.38,-1162.5 v1(-1609.84,-1162.5) v1(-1609.84,-1178.66) v1(-1609.84,-1195) ; C303C.1@-1657.38,-262.5 v1(-1609.84,-262.5) v1(-1609.84,-278.66) v1(-1609.84,-295) ; C303B.1@-1657.38,637.5 v1(-1609.84,637.5) v1(-1609.84,621.34) v1(-1609.84,605) ; C303A.1@-1657.38,1537.5 v1(-1609.84,1537.5) v1(-1609.84,1521.34) v1(-1609.84,1505) ; v1@-1590.68,-1162.8 C291D.1@-1543.14,-1162.8 ; v1@-1590.68,-262.8 C291C.1@-1543.14,-262.8 ; v1@-1590.68,637.2 C291B.1@-1543.14,637.2 ; v1(-1590.16,-1195) v1(-1590.16,-1178.66) v1(-1590.16,-1162.5) ; v1(-1590.16,-295) v1(-1590.16,-278.66) v1(-1590.16,-262.5) ; v1(-1590.16,605) v1(-1590.16,621.34) v1(-1590.16,637.5) ; v1(-1590.16,1505) v1(-1590.16,1521.34) v1(-1590.16,1537.5) ; v1@-1588.18,1537.2 C291A.1@-1540.64,1537.2 ; U93D.5@-1546.85,-1512.5 -1522.5,-1512.5 ccw(c-1522.5,-1500) v1(-1510,-1500) C299D.1@-1495,-1500 ; U93C.5@-1546.85,-612.5 -1522.5,-612.5 ccw(c-1522.5,-600) v1(-1510,-600) C299C.1@-1495,-600 ; U93B.5@-1546.85,287.5 -1522.5,287.5 ccw(c-1522.5,300) v1(-1510,300) C299B.1@-1495,300 ; U93A.5@-1546.85,1187.5 -1522.5,1187.5 ccw(c-1522.5,1200) v1(-1510,1200) C299A.1@-1495,1200 ; U89D.2@-1437.5,-1296.85 -1437.5,-1272.5 cw(c-1425,-1272.5) v1(-1425,-1260) C295D.2@-1425,-1245 ; U89C.2@-1437.5,-396.85 -1437.5,-372.5 cw(c-1425,-372.5) v1(-1425,-360) C295C.2@-1425,-345 ; U89B.2@-1437.5,503.15 -1437.5,527.5 cw(c-1425,527.5) v1(-1425,540) C295B.2@-1425,555 ; U89A.2@-1437.5,1403.15 -1437.5,1427.5 cw(c-1425,1427.5) v1(-1425,1440) C295A.2@-1425,1455 ; v1(-1340,-1222.05) -1335.55,-1222.05 -1316.48,-1222.05 ccw(c-1316.48,-1218.06) C287D.2@-1312.5,-1218.06 ; v1(-1340,-322.05) -1335.55,-322.05 -1316.48,-322.05 ccw(c-1316.48,-318.06) C287C.2@-1312.5,-318.06 ; v1(-1340,577.95) -1335.55,577.95 -1316.48,577.95 ccw(c-1316.48,581.94) C287B.2@-1312.5,581.94 ; v1(-1340,1477.95) -1335.55,1477.95 -1316.48,1477.95 ccw(c-1316.48,1481.94) C287A.2@-1312.5,1481.94 ; v15(-343.75,-1281.26) cw(c-343.75,-1306.85) -318.16,-1306.85 R303.2@-318.16,-1331.25 C272.2@-318.16,-1368.75 -318.16,-1418.45 ccw(c-305.36,-1418.45) C267.1@-305.36,-1431.25 ; C14.2@1250,275.56 ccw(c1281.54,307.1) 1281.54,262.5 v4(1368.75,262.5) ; C11.2@1250,599.44 v4(1250,615) ; v4(1468.75,512.5) 1555.96,512.5 cw(c1555.96,467.9) C13.2@1587.5,499.44 ; v4(1587.5,160) C9.2@1587.5,175.56 ; C12.2@1686.94,218.75 ccw(c1655.4,250.29) 1700,250.29 U85.3@1700,285.14 ; C12.2@1687.5,218.75 v4(1702.5,218.75) ; C10.2@1786.94,556.25 v4(1802.5,556.25)
  Bottom Layer w15: v4(2043.75,0.3) 2047.12,0.3 cw(c2047.12,-45.41) R239.1@2079.44,-13.09 ; v4(2043.75,400.3) 2047.12,400.3 cw(c2047.12,354.59) R240.1@2079.44,386.91
  Bottom Layer w16: v4(2043.75,-1599.7) 2061.61,-1599.7 cw(c2061.61,-1613.09) R241.2@2075,-1613.09 ; v4(2043.75,-1199.7) 2061.61,-1199.7 cw(c2061.61,-1213.09) R242.1@2075,-1213.09
  Bottom Layer w20: C480.1@-3008.46,-512.5 cw(c-2983.63,-512.5) -3001.2,-494.95 v1(-2987.5,-481.25) v1(-2975,-468.75) v1(-2962.5,-456.25) -2948.81,-442.56 ccw(c-2966.37,-425) C479.1@-2941.54,-425 ; C315D.2@-2005.6,-1655.6 ccw(c-2002.43,-1655.6) C315D.2@-2004.67,-1657.83 ; C315C.2@-2005.6,-755.6 ccw(c-2002.43,-755.6) C315C.2@-2004.67,-757.83 ; C315B.2@-2005.6,144.4 ccw(c-2002.43,144.4) C315B.2@-2004.67,142.17 ; C315A.2@-2005.6,1044.4 ccw(c-2002.43,1044.4) C315A.2@-2004.67,1042.17 ; C311D.2@-1907.83,-1754.67 ccw(c-1905.6,-1752.43) C311D.2@-1905.6,-1755.6 ; C311C.2@-1907.83,-854.67 ccw(c-1905.6,-852.43) C311C.2@-1905.6,-855.6 ; C311B.2@-1907.83,45.33 ccw(c-1905.6,47.57) C311B.2@-1905.6,44.4 ; C311A.2@-1907.83,945.33 ccw(c-1905.6,947.57) C311A.2@-1905.6,944.4 ; C198.1@512.5,-916.54 629.56,-916.54 cw(c629.56,-945.44) v3(650,-925) ; C195.1@546.06,-1562.5 558.21,-1574.65 cw(c487.5,-1645.36) 587.5,-1645.36 v3(587.5,-1702.5) ; C196.1@563.78,-1270.69 563.78,-1320.23 ccw(c644.77,-1320.23) v3(587.5,-1377.5) ; v3(937.5,-1275) C181.1@937.5,-1213.39
  Bottom Layer w25: D9.2@1724.46,-1650 v7(1781.25,-1650) C481.2@1838.63,-1650 ; D8.1@1724.46,-975 v7(1781.25,-975) C482.1@1838.63,-975
  other v1: -1337.5,-1900 -1337.5,-1862.5 -2712.61,-1775.14 -2700.11,-1775.14 -2687.61,-1775.14 -2675.11,-1775.14 -2662.61,-1775.14 -2650.11,-1775.14 -2637.61,-1775.14 -2625.11,-1775.14 -2312.61,-1775.14 -2300.11,-1775.14 -2287.61,-1775.14 -2275.11,-1775.14 -2262.61,-1775.14 -2250.11,-1775.14 -2237.61,-1775.14 -2225.11,-1775.14 -1262.5,-1725 -1250,-1712.5 -1967.5,-1707.5 -1237.5,-1700 -1977.5,-1697.5 -1987.5,-1687.5 -1225,-1687.5 -2712.61,-1600.14 -2700.11,-1600.14 -2687.61,-1600.14 -2675.11,-1600.14 -2662.61,-1600.14 -2650.11,-1600.14 -2637.61,-1600.14 -2312.61,-1600.14 -2300.11,-1600.14 -2287.61,-1600.14 -2275.11,-1600.14 -2262.61,-1600.14 -2250.11,-1600.14 -2237.61,-1600.14 -2712.61,-1550.14 -2700.11,-1550.14 -2687.61,-1550.14 -2675.11,-1550.14 -2662.61,-1550.14 -2650.11,-1550.14 -2637.61,-1550.14 -2625.11,-1550.14 -2312.61,-1550.14 -2300.11,-1550.14 -2287.61,-1550.14 -2275.11,-1550.14 -2262.61,-1550.14 -2250.11,-1550.14 -2237.61,-1550.14 -2225.11,-1550.14 -3150,-1412.5 -2712.61,-1375.14 -2700.11,-1375.14 -2687.61,-1375.14 -2675.11,-1375.14 -2662.61,-1375.14 -2650.11,-1375.14 -2637.61,-1375.14 -2312.61,-1375.14 -2300.11,-1375.14 -2287.61,-1375.14 -2275.11,-1375.14 -2262.61,-1375.14 -2250.11,-1375.14 -2237.61,-1375.14 -2712.61,-1325.14 -2700.11,-1325.14 -2687.61,-1325.14 -2675.11,-1325.14 -2662.61,-1325.14 -2650.11,-1325.14 -2637.61,-1325.14 -2625.11,-1325.14 -2312.61,-1325.14 -2300.11,-1325.14 -2287.61,-1325.14 -2275.11,-1325.14 -2262.61,-1325.14 -2250.11,-1325.14 -2237.61,-1325.14 -2225.11,-1325.14 -2712.61,-1150.14 -2700.11,-1150.14 -2687.61,-1150.14 -2675.11,-1150.14 -2662.61,-1150.14 -2650.11,-1150.14 -2637.61,-1150.14 -2312.61,-1150.14 -2300.11,-1150.14 -2287.61,-1150.14 -2275.11,-1150.14 -2262.61,-1150.14 -2250.11,-1150.14 -2237.61,-1150.14 -2712.61,-1100.14 -2700.11,-1100.14 -2687.61,-1100.14 -2675.11,-1100.14 -2662.61,-1100.14 -2650.11,-1100.14 -2637.61,-1100.14 -2625.11,-1100.14 -2312.61,-1100.14 -2300.11,-1100.14 -2287.61,-1100.14 -2275.11,-1100.14 -2262.61,-1100.14 -2250.11,-1100.14 -2237.61,-1100.14 -2225.11,-1100.14 -1987.5,-1012.5 -1212.5,-1012.5 -1977.5,-1002.5 -1967.5,-992.5 -1237.5,-987.5 -1262.5,-962.5 -2712.61,-925.14 -2700.11,-925.14 -2687.61,-925.14 -2675.11,-925.14 -2662.61,-925.14 -2650.11,-925.14 -2637.61,-925.14 -2312.61,-925.14 -2300.11,-925.14 -2287.61,-925.14 -2275.11,-925.14 -2262.61,-925.14 -2250.11,-925.14 -2237.61,-925.14 -2712.61,-875.14 -2700.11,-875.14 -2687.61,-875.14 -2675.11,-875.14 -2662.61,-875.14 -2650.11,-875.14 -2637.61,-875.14 -2625.11,-875.14 -2312.61,-875.14 -2300.11,-875.14 -2287.61,-875.14 -2275.11,-875.14 -2262.61,-875.14 -2250.11,-875.14 -2237.61,-875.14 -2225.11,-875.14 -1262.5,-837.5 -1237.5,-812.5 -1970,-805 -1982.5,-792.5 -1212.5,-787.5 -1987.5,-775 -2312.61,-700.14 -2300.11,-700.14 -2287.61,-700.14 -2275.11,-700.14 -2262.61,-700.14 -2250.11,-700.14 -2237.61,-700.14 -2712.5,-700 -2700,-700 -2687.5,-700 -2675,-700 -2662.5,-700 -2650,-700 -2637.5,-700 -2312.61,-650.14 -2300.11,-650.14 -2287.61,-650.14 -2275.11,-650.14 -2262.61,-650.14 -2250.11,-650.14 -2237.61,-650.14 -2225.11,-650.14 -2712.5,-650 -2700,-650 -2687.5,-650 -2675,-650 -2662.5,-650 -2650,-650 -2637.5,-650 -2625,-650 -2312.61,-475.14 -2300.11,-475.14 -2287.61,-475.14 -2275.11,-475.14 -2262.61,-475.14 -2250.11,-475.14 -2237.61,-475.14 -2712.5,-475 -2700,-475 -2687.5,-475 -2675,-475 -2662.5,-475 -2650,-475 -2637.5,-475 -2712.61,-425.14 -2700.11,-425.14 -2687.61,-425.14 -2675.11,-425.14 -2662.61,-425.14 -2650.11,-425.14 -2637.61,-425.14 -2625.11,-425.14 -2312.61,-425.14 -2300.11,-425.14 -2287.61,-425.14 -2275.11,-425.14 -2262.61,-425.14 -2250.11,-425.14 -2237.61,-425.14 -2225.11,-425.14 -2712.61,-250.14 -2700.11,-250.14 -2687.61,-250.14 -2675.11,-250.14 -2662.61,-250.14 -2650.11,-250.14 -2637.61,-250.14 -2312.5,-250 -2300,-250 -2287.5,-250 -2275,-250 -2262.5,-250 -2250,-250 -2237.5,-250 -2712.61,-200.14 -2700.11,-200.14 -2687.61,-200.14 -2675.11,-200.14 -2662.61,-200.14 -2650.11,-200.14 -2637.61,-200.14 -2625.11,-200.14 -2312.5,-200 -2300,-200 -2287.5,-200 -2275,-200 -2262.5,-200 -2250,-200 -2237.5,-200 -2225,-200 -2000,-125 -1987.5,-112.5 -1212.5,-112.5 -1975,-100 -1237.5,-87.5 -1262.5,-62.5 -2712.61,-25.14 -2700.11,-25.14 -2687.61,-25.14 -2675.11,-25.14 -2662.61,-25.14 -2650.11,-25.14 -2637.61,-25.14 -2312.5,-25 -2300,-25 -2287.5,-25 -2275,-25 -2262.5,-25 -2250,-25 -2237.5,-25 -2712.61,24.86 -2700.11,24.86 -2687.61,24.86 -2675.11,24.86 -2662.61,24.86 -2650.11,24.86 -2637.61,24.86 -2625.11,24.86 -2312.61,24.86 -2300.11,24.86 -2287.61,24.86 -2275.11,24.86 -2262.61,24.86 -2250.11,24.86 -2237.61,24.86 -2225.11,24.86 -1262.5,62.5 -1237.5,87.5 -1970,95 -1982.5,107.5 -1212.5,112.5 -1987.5,125 -2712.61,199.86 -2700.11,199.86 -2687.61,199.86 -2675.11,199.86 -2662.61,199.86 -2650.11,199.86 -2637.61,199.86 -2312.61,199.86 -2300.11,199.86 -2287.61,199.86 -2275.11,199.86 -2262.61,199.86 -2250.11,199.86 -2237.61,199.86 -3098.92,214.86 -2712.61,249.86 -2700.11,249.86 -2687.61,249.86 -2675.11,249.86 -2662.61,249.86 -2650.11,249.86 -2637.61,249.86 -2625.11,249.86 -2312.61,249.86 -2300.11,249.86 -2287.61,249.86 -2275.11,249.86 -2262.61,249.86 -2250.11,249.86 -2237.61,249.86 -2225.11,249.86 -2712.61,424.86 -2700.11,424.86 -2687.61,424.86 -2675.11,424.86 -2662.61,424.86 -2650.11,424.86 -2637.61,424.86 -2312.61,424.86 -2300.11,424.86 -2287.61,424.86 -2275.11,424.86 -2262.61,424.86 -2250.11,424.86 -2237.61,424.86 -2712.61,474.86 -2700.11,474.86 -2687.61,474.86 -2675.11,474.86 -2662.61,474.86 -2650.11,474.86 -2637.61,474.86 -2625.11,474.86 -2312.61,474.86 -2300.11,474.86 -2287.61,474.86 -2275.11,474.86 -2262.61,474.86 -2250.11,474.86 -2237.61,474.86 -2225.11,474.86 -3065,568.75 -3028.75,568.75 -2712.61,649.86 -2700.11,649.86 -2687.61,649.86 -2675.11,649.86 -2662.61,649.86 -2650.11,649.86 -2637.61,649.86 -2312.61,649.86 -2300.11,649.86 -2287.61,649.86 -2275.11,649.86 -2262.61,649.86 -2250.11,649.86 -2237.61,649.86 -2712.61,699.86 -2700.11,699.86 -2687.61,699.86 -2675.11,699.86 -2662.61,699.86 -2650.11,699.86 -2637.61,699.86 -2625.11,699.86 -2312.61,699.86 -2300.11,699.86 -2287.61,699.86 -2275.11,699.86 -2262.61,699.86 -2250.11,699.86 -2237.61,699.86 -2225.11,699.86 -3036.25,731.25 -2000,775 -1987.5,787.5 -1212.5,787.5 -1975,800 -1237.5,812.5 -1262.5,837.5 -2712.61,874.86 -2700.11,874.86 -2687.61,874.86 -2675.11,874.86 -2662.61,874.86 -2650.11,874.86 -2637.61,874.86 -2312.61,874.86 -2300.11,874.86 -2287.61,874.86 -2275.11,874.86 -2262.61,874.86 -2250.11,874.86 -2237.61,874.86 -2712.61,924.86 -2700.11,924.86 -2687.61,924.86 -2675.11,924.86 -2662.61,924.86 -2650.11,924.86 -2637.61,924.86 -2625.11,924.86 -2312.61,924.86 -2300.11,924.86 -2287.61,924.86 -2275.11,924.86 -2262.61,924.86 -2250.11,924.86 -2237.61,924.86 -2225.11,924.86 -1262.5,962.5 -1237.5,987.5 -1970,995 -1982.5,1007.5 -1212.5,1012.5 -1987.5,1025 -2712.61,1099.86 -2700.11,1099.86 -2687.61,1099.86 -2675.11,1099.86 -2662.61,1099.86 -2650.11,1099.86 -2637.61,1099.86 -2312.61,1099.86 -2300.11,1099.86 -2287.61,1099.86 -2275.11,1099.86 -2262.61,1099.86 -2250.11,1099.86 -2237.61,1099.86 -2712.61,1149.86 -2700.11,1149.86 -2687.61,1149.86 -2675.11,1149.86 -2662.61,1149.86 -2650.11,1149.86 -2637.61,1149.86 -2625.11,1149.86 -2312.61,1149.86 -2300.11,1149.86 -2287.61,1149.86 -2275.11,1149.86 -2262.61,1149.86 -2250.11,1149.86 -2237.61,1149.86 -2225.11,1149.86 -2712.61,1324.86 -2700.11,1324.86 -2687.61,1324.86 -2675.11,1324.86 -2662.61,1324.86 -2650.11,1324.86 -2637.61,1324.86 -2312.61,1324.86 -2300.11,1324.86 -2287.61,1324.86 -2275.11,1324.86 -2262.61,1324.86 -2250.11,1324.86 -2237.61,1324.86 -2712.61,1374.86 -2700.11,1374.86 -2687.61,1374.86 -2675.11,1374.86 -2662.61,1374.86 -2650.11,1374.86 -2637.61,1374.86 -2625.11,1374.86 -2312.61,1374.86 -2300.11,1374.86 -2287.61,1374.86 -2275.11,1374.86 -2262.61,1374.86 -2250.11,1374.86 -2237.61,1374.86 -2225.11,1374.86 -2712.5,1550 -2700,1550 -2687.5,1550 -2675,1550 -2662.5,1550 -2650,1550 -2637.5,1550 -2312.5,1550 -2300,1550 -2287.5,1550 -2275,1550 -2262.5,1550 -2250,1550 -2237.5,1550 -2712.5,1600 -2700,1600 -2687.5,1600 -2675,1600 -2662.5,1600 -2650,1600 -2637.5,1600 -2625,1600 -2312.5,1600 -2300,1600 -2287.5,1600 -2275,1600 -2262.5,1600 -2250,1600 -2237.5,1600 -2225,1600 -2000,1675 -1987.5,1687.5 -1212.5,1687.5 -1975,1700 -1237.5,1712.5 -1262.5,1737.5 -2712.5,1775 -2700,1775 -2687.5,1775 -2675,1775 -2662.5,1775 -2650,1775 -2637.5,1775 -2312.5,1775 -2300,1775 -2287.5,1775 -2275,1775 -2262.5,1775 -2250,1775 -2237.5,1775
  other v3: 700.59,-1612.5 -222.44,-1542.77 -222.44,-1525 700.59,-1462.5 1812.5,-356.25 1812.5,-268.75 1812.5,25 2137.5,340 2162.5,340 2187.5,340 2137.5,362.5 2187.5,362.5 2137.5,412.5 2187.5,412.5 2162.5,435 2187.5,435 2137.5,540 2162.5,540 2187.5,540 2137.5,562.5 2187.5,562.5 2137.5,612.5 2187.5,612.5 2137.5,635 2162.5,635 2187.5,635
  other v4: 2137.5,-1262.5 2162.5,-1262.5 2187.5,-1262.5 2137.5,-1237.5 2187.5,-1237.5 2137.5,-1187.5 2187.5,-1187.5 2137.5,-1162.5 2162.5,-1162.5 2187.5,-1162.5 2137.5,-1062.5 2162.5,-1062.5 2187.5,-1062.5 2137.5,-1037.5 2187.5,-1037.5 2043.75,-999.7 2137.5,-987.5 2187.5,-987.5 2162.5,-962.5 2187.5,-962.5 2137.5,-460 2162.5,-460 2187.5,-460 2137.5,-437.5 2187.5,-437.5 2137.5,-387.5 2187.5,-387.5 2162.5,-365 2187.5,-365 2137.5,-260 2162.5,-260 2187.5,-260 2137.5,-237.5 2187.5,-237.5 2137.5,-187.5 2187.5,-187.5 2137.5,-165 2162.5,-165 2187.5,-165 2137.5,-60 2162.5,-60 2187.5,-60 2137.5,-37.5 2187.5,-37.5 2137.5,12.5 2187.5,12.5 2162.5,35 2187.5,35
  other v5: -1687.5,-1437.5 -1600,-1437.5 -1512.5,-1437.5 -1687.5,-1350 -1512.5,-1350 -1687.5,-1262.5 -1600,-1262.5 -1512.5,-1262.5 -1687.5,-537.5 -1600,-537.5 -1512.5,-537.5 -1687.5,-450 -1512.5,-450 -1687.5,-362.5 -1600,-362.5 -1512.5,-362.5 -1687.5,362.5 -1600,362.5 -1512.5,362.5 -1687.5,450 -1512.5,450 -1687.5,537.5 -1600,537.5 -1512.5,537.5 -1687.5,1262.5 -1600,1262.5 -1512.5,1262.5 -1687.5,1350 -1512.5,1350 -1687.5,1437.5 -1600,1437.5 -1512.5,1437.5
  other v7: 1737.5,-1312.36 1937.5,-1312.36
  other v9: 2162.5,-1212.5 2162.5,-1012.5 2162.5,-412.5 2162.5,-212.5 2162.5,-12.5
  other v10: -1600,-1350 -1600,-450 -1600,450 -1600,1350
  other v11: -402.81,-1300.94 -284.69,-1300.94 -402.81,-1261.57 -284.69,-1261.57
  other v13: 2162.5,387.5 2162.5,587.5
ANALOG1.A1_N: C351C.1 P1.80 R351C.2 | length 2309.1
  Int5 (ST) w6: P1.80@-3427.3,537.5 -3310.3,537.5 ccw(c-3277.3,537.5) -3253.97,514.17 -3147.53,620.6 ccw(c-3201.93,675) -3125,675 -3125,754.29 cw(c-3039.64,754.29) -3100,814.64 ccw(c-3160.36,875) -3075,875 -3075,954.29 cw(c-2989.64,954.29) -3050,1014.64 ccw(c-3110.36,1075) -3025,1075 -3025,1152.14 cw(c-2939.64,1152.14) -3000,1212.5 ccw(c-3060.36,1272.86) -2975,1272.86 -2975,1352.14 cw(c-2889.64,1352.14) -2950,1412.5 ccw(c-3010.36,1472.86) -2925,1472.86 -2925,1552.14 cw(c-2839.64,1552.14) -2900,1612.5 ccw(c-2960.36,1672.86) -2875,1672.86 -2875,1762.5 cw(c-2825,1762.5) -2825,1812.5 -2425,1812.5 cw(c-2425,1750) -2362.5,1750 -2362.5,1737.5 ccw(c-2332.5,1737.5) -2332.5,1707.5 v1(-2317.5,1707.5)
  Bottom Layer w9: v1(-2317.5,1707.5) -2300,1690 C351C.1@-2300,1688.09 -2250.59,1737.5 R351C.2@-2249.41,1737.5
